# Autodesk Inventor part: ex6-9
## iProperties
Shininess: 64.0
Length Units: 11272
Angle Units: 11279
Time Units: 11290
Mass Units: 11286
Length Display Precision: 3
Angle Display Precision: 2
Compacted: True
Part Number: ex6-9
Document SubType Name: Modeling
Created: 2002-09
Designer: Elise Moss
Density: 0.0
Volumn: 0.0
Area: 0.0
PropertySet Name: Model Information
Control State: 0
Master: False
Checked Out: False
Author: Elise Moss
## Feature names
1. Revolution1
2. Shell1
3. Hole1
4. Loft1
5. Sweep1
6. Coil1
